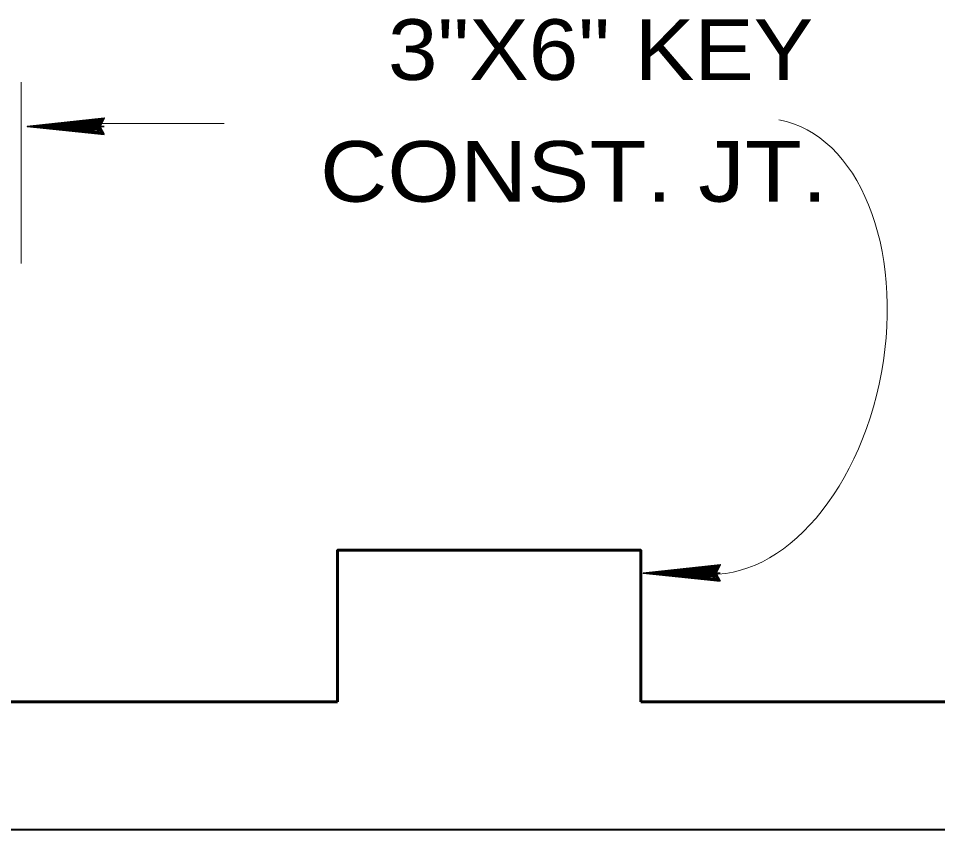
# Model space of a CAD drawing. Extents: x 4.49 to 7.69, y 0.28 to 2.27.
# Drawn here: x 5.9583 to 6.0846, y 1.9381 to 2.0496 of the extents above; entities that cross this region are included whole.
import ezdxf

# ---------------------------------------------------------------- set-up
doc = ezdxf.new("R2010")
doc.units = 0
doc.header["$LTSCALE"] = 0.0033
doc.layers.add('1', color=7, linetype='Continuous', lineweight=35)

msp = doc.modelspace()

# ---------------------------------------------------------------- linework, layer by layer
at = {"layer": '1', "lineweight": 13}
for p, q in [((5.958667, 2.015917), (5.958667, 2.040833)), ((5.96575, 2.035167), (5.986583, 2.035167))]:
    msp.add_line(p, q, dxfattribs=at)
at = {"layer": '1'}
for p, q in [((5.969833, 2.035833), (5.9625, 2.035)), ((5.969833, 2.035667), (5.9625, 2.034917)), ((5.969833, 2.035583), (5.9625, 2.03475)), ((5.969917, 2.035417), (5.962583, 2.034667)), ((5.970083, 2.03475), (5.9595, 2.03475)), ((5.969833, 2.033917), (5.962, 2.034917)), ((5.969833, 2.033917), (5.962, 2.03475)), ((5.969833, 2.03375), (5.962, 2.034667)), ((5.969833, 2.03375), (5.962, 2.034667)), ((5.969833, 2.033833), (5.962, 2.034667)), ((6.0545, 1.9725), (6.046667, 1.9735)), ((6.0545, 1.974417), (6.047167, 1.973583)), ((6.0545, 1.97425), (6.047167, 1.9735)), ((6.0545, 1.974167), (6.047167, 1.973333)), ((6.054583, 1.974), (6.04725, 1.97325)), ((6.05475, 1.973333), (6.044167, 1.973333)), ((6.0545, 1.9725), (6.046667, 1.973333)), ((6.0545, 1.972333), (6.046667, 1.97325)), ((6.0545, 1.972333), (6.046667, 1.97325)), ((6.0545, 1.972417), (6.046667, 1.97325))]:
    msp.add_line(p, q, dxfattribs=at)
at = {"layer": '1', "lineweight": 60}
for p, q in [((5.939667, 1.955667), (6.002167, 1.955667)), ((6.106333, 1.955667), (6.043833, 1.955667))]:
    msp.add_line(p, q, dxfattribs=at)
at = {"layer": '1', "lineweight": 40}
msp.add_line((5.87425, 1.938083), (6.172, 1.938083), dxfattribs=at)
at = {"layer": '1'}
for points in [[(5.970083, 2.033667), (5.9595, 2.03475), (5.970083, 2.035917), (5.9695, 2.03475)], [(5.969333, 2.034667), (5.964667, 2.034583), (5.964667, 2.034667), (5.965583, 2.034667), (5.969333, 2.034583), (5.966333, 2.0345), (5.9695, 2.034417), (5.96725, 2.034333), (5.9695, 2.03425), (5.966, 2.0345), (5.961333, 2.034667), (5.96225, 2.034917), (5.961, 2.034917), (5.969333, 2.034917), (5.966917, 2.035083), (5.9695, 2.035083), (5.964167, 2.034667), (5.9695, 2.035333)], [(6.05475, 1.97225), (6.044167, 1.973333), (6.05475, 1.9745), (6.054167, 1.973333)], [(6.054, 1.97325), (6.049333, 1.973167), (6.049333, 1.97325), (6.05025, 1.97325), (6.054, 1.973167), (6.051, 1.973083), (6.054167, 1.973), (6.051917, 1.972917), (6.054167, 1.972833), (6.050667, 1.973083), (6.046, 1.97325), (6.046917, 1.9735), (6.045667, 1.9735), (6.054, 1.9735), (6.051583, 1.973667), (6.054167, 1.973667), (6.048833, 1.97325), (6.054167, 1.973917)]]:
    msp.add_lwpolyline(points, close=True, dxfattribs=at)
for points in [[(5.969333, 2.034667), (5.96975, 2.033917), (5.9695, 2.034167), (5.969333, 2.0345), (5.969083, 2.034417), (5.96925, 2.034083), (5.969417, 2.034833), (5.969583, 2.035333), (5.969833, 2.03575)], [(6.054, 1.97325), (6.054417, 1.9725), (6.054167, 1.97275), (6.054, 1.973083), (6.05375, 1.973), (6.053917, 1.972667), (6.054083, 1.973417), (6.05425, 1.973917), (6.0545, 1.974333)]]:
    msp.add_lwpolyline(points, dxfattribs=at)
at = {"layer": '1', "lineweight": 60}
msp.add_lwpolyline([(6.002167, 1.955667), (6.002167, 1.9765), (6.043833, 1.9765), (6.043833, 1.955667)], dxfattribs=at)
at = {"layer": '1', "lineweight": 13}
msp.add_ellipse((6.057125, 2.004542), major_axis=(0.005708, 0.031125), ratio=0.635583, start_param=3.1415927, end_param=6.2831853, dxfattribs=at)

# ---------------------------------------------------------------- texts
at = {"layer": '1'}
for s, width, p in [('3"X6" KEY', 1.1, (6.009083, 2.041167)), ('CONST. JT. ', 1.15, (5.99975, 2.024417))]:
    msp.add_text(s, height=0.008334, dxfattribs=dict(at, width=width)).set_placement(p)

doc.saveas('drawing.dxf')
